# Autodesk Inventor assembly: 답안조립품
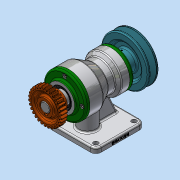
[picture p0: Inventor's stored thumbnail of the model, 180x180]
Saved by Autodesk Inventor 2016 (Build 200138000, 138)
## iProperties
Created: 2019-01
Part Number: 답안조립품
Material: 일반
Document SubType Name: Assembly
Designer: Administrator
Author: Administrator
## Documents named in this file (15)
- C:\Users\Administrator\Desktop\490108V1014\답안조립품.iam
- C:\Users\Administrator\Desktop\490108V1014\본체.ipt
- C:\Users\Administrator\Desktop\490108V1014\베어링 6203.ipt
- C:\Users\Administrator\Desktop\490108V1014\축.ipt
- C:\Users\Administrator\Desktop\490108V1014\뒤커버.ipt
- C:\Users\Administrator\Desktop\490108V1014\오일 실 17 30 8.ipt
- C:\Users\Administrator\Desktop\490108V1014\키 5 x 5 x 20.ipt
- C:\Users\Administrator\Desktop\490108V1014\멈춤나사 M3.ipt
- C:\Users\Administrator\Desktop\490108V1014\V-벨트풀리.ipt
- C:\Users\Administrator\Desktop\490108V1014\볼트 M4.ipt
- C:\Users\Administrator\Desktop\490108V1014\베어링 6205.ipt
- C:\Users\Administrator\Desktop\490108V1014\앞커버.ipt
- C:\Users\Administrator\Desktop\490108V1014\오일 실 25 38 8.ipt
- C:\Users\Administrator\Desktop\490108V1014\스퍼기어.ipt
- C:\Users\Administrator\Desktop\490108V1014\키 6 x 6 x 18.ipt
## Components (1 placed, 1 different names)
1. V-벨트풀리:1
